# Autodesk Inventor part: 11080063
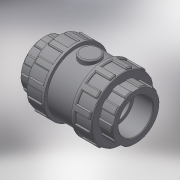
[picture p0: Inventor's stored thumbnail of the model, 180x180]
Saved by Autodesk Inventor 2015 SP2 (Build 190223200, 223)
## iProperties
Created: 2017-11
Part Number: 11080063
Material: Generic
Description: PLASSON CHECK VALVE CEM 63 PTFE COATED SPRING + EPDM O-RING
Document SubType Name: Modeling
Designer: KIM
Density: 1 g/cm^3
Appearance: Default
Author: KIM
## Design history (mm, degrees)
derived "110800 - 110600 110900-110000.ipt"
feature "Solid1::110800 - 110600 110900-110000.ipt"
tag "TaggingFeature1"
body "Solid1"
other parameters: "d0" = 169, "d1" = 63, "d2" = 118, "d3" = 38, "d4" = 50.4, "d5" = 26.6, "d7" = 88.2, "d8" = 106.2, "d13" = 1.89, "d23" = 38, "d24" = 113.28, "d25" = 1.26, "d26" = 1.89, "d27" = 17.7, "d28" = 8.85, "d29" = 28.5, "d30" = 0, "d35" = 1.89, "d39" = 59, "d45" = 360 deg, "d47" = 1.26, "d50" = 59, "d51" = 35.4, "d53" = 0, "d54" = 2.36, "d55" = 12.6, "d56" = 6.3, "d57" = 26.6, "d58" = 0, "d59" = 1.89, "d61" = 360 deg, "d_" = 63, "l_" = 38, "H_" = 169, "K_" = 118
